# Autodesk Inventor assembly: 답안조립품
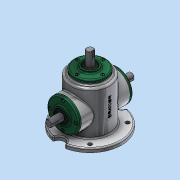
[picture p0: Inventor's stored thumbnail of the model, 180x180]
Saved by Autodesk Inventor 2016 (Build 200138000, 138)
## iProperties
Created: 2018-04
Part Number: 답안조립품
Material: 일반
Document SubType Name: Assembly
Designer: Administrator
Author: Administrator
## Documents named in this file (16)
- C:\Users\Administrator\Desktop\480407V1030\답안조립품.iam
- C:\Users\Administrator\Desktop\480407V1030\본체.ipt
- C:\Users\Administrator\Desktop\480407V1030\메인 축.ipt
- 메인 축.ipt
- C:\Users\Administrator\Desktop\480407V1030\베어링 6203.ipt
- C:\Users\Administrator\Desktop\480407V1030\커버.ipt
- C:\Users\Administrator\Desktop\480407V1030\오일 실.ipt
- 오일 실.ipt
- C:\Users\Administrator\Desktop\480407V1030\서브 축.ipt
- 서브 축.ipt
- C:\Users\Administrator\Desktop\480407V1030\키 5x5.ipt
- C:\Users\Administrator\Desktop\480407V1030\메인 베벨기어.ipt
- C:\Users\Administrator\Desktop\480407V1030\키 4x4.ipt
- C:\Users\Administrator\Desktop\480407V1030\서브 베벨기어.ipt
- C:\Users\Administrator\Desktop\480407V1030\볼트 M4.ipt
- 볼트 M4.ipt
